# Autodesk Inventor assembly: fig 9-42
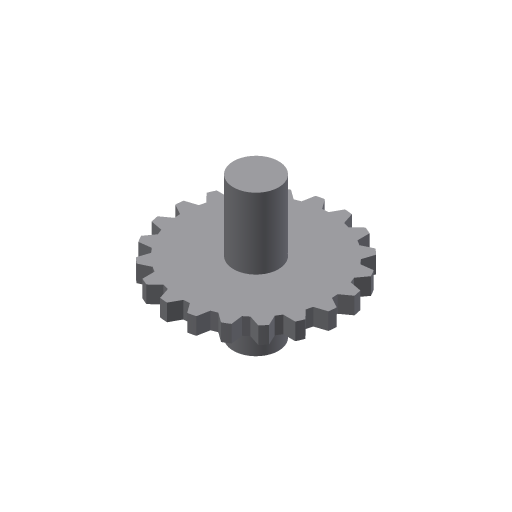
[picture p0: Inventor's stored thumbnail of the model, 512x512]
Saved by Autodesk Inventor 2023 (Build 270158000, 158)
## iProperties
Created: 2013-07
Part Number: fig 9-42
Document SubType Name: Assembly
Designer: CADCIM
Author: CADCIM
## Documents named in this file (3)
- D:\PROJECTS\Project 2022\Autodesk Inventor For Professional 2023\RESOURCES INVENTOR 2023\RESOURCES INVENTOR 2023\Inventor_2023_Part\Inventor_2023_Part\c09_Inv_2023_prt\fig 9-43.iam
- D:\PROJECTS\Project 2022\Autodesk Inventor For Professional 2023\RESOURCES INVENTOR 2023\RESOURCES INVENTOR 2023\Inventor_2023_Part\Inventor_2023_Part\c09_Inv_2023_prt\13.ipt
- D:\PROJECTS\Project 2022\Autodesk Inventor For Professional 2023\RESOURCES INVENTOR 2023\RESOURCES INVENTOR 2023\Inventor_2023_Part\Inventor_2023_Part\c09_Inv_2023_prt\14.ipt
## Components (2 placed, 2 different names)
1. 13:1 — Rotational:1
2. 14:1 — Rotational:1
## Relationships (1: RevoluteJoint 1)
- Rotational:1 [RevoluteJoint]: 13:1 ↔ 14:1
